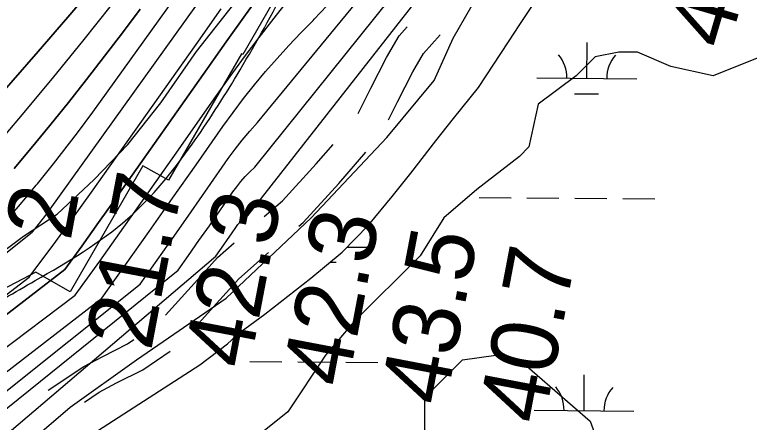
# Model space of a CAD drawing. Extents: x 3271442 to 3309282, y 752266 to 777610.
# Drawn here: x 3289402 to 3290138, y 762104 to 762512 of the extents above; entities that cross this region are included whole.
import ezdxf

# ---------------------------------------------------------------- set-up
doc = ezdxf.new("R2010")
doc.units = 0
for name, color, linetype in [('V-RIVR-EDGE', 7, 'Continuous'), ('V-RIVR-RANG', 7, 'Continuous'), ('V-ROAD-CNTR', 7, 'Continuous'), ('V-RRAP-FSHR', 7, 'Continuous'), ('V-RRAP-RVMT', 7, 'Continuous'), ('V-SITE-VEGE', 7, 'Continuous'), ('V-TOPO-DPTH', 7, 'Continuous'), ('V-TOPO-MAJR', 7, 'Continuous'), ('V-TOPO-MINR', 7, 'Continuous'), ('V-TOPO-WATR', 7, 'Continuous'), ('V-WETL-SWMP', 7, 'Continuous')]:
    doc.layers.add(name, color=color, linetype=linetype)

msp = doc.modelspace()

# ---------------------------------------------------------------- linework, layer by layer
at = {"layer": 'V-RIVR-EDGE'}
msp.add_lwpolyline([(3289379.09, 762266.5), (3289410.88, 762289.9), (3289444.84, 762311.98), (3289481.88, 762346.66), (3289515.43, 762381.79), (3289548.57, 762423.44), (3289584.34, 762475.08), (3289630.13, 762533.64), (3289660.19, 762562.26), (3289673.75, 762594.39), (3289701.73, 762662.13), (3289707, 762682.55), (3289727.55, 762729.01), (3289737.6, 762751.59), (3289752.44, 762776.33), (3289772.05, 762795.84), (3289795.16, 762824.04), (3289831.33, 762864.37), (3289858.8, 762898.21), (3289943.82, 763003.19), (3289978.7, 763046.14), (3290011.41, 763088.22), (3290036.7, 763119.89)], dxfattribs=at)
at = {"layer": 'V-ROAD-CNTR'}
for points in [[(3289745.91, 762413.02), (3289758.8, 762438.14), (3289774.28, 762468.94), (3289786.95, 762490.54), (3289795.09, 762499.69)], [(3289776.38, 762406.69), (3289785.55, 762424.56), (3289800.64, 762454.6), (3289811.33, 762472.81), (3289828.07, 762491.62)], [(3289652.03, 762309.69), (3289670.15, 762325.39), (3289704.1, 762362.56), (3289720.9, 762381.98)], [(3289686.64, 762299.98), (3289691.12, 762303.86), (3289726.53, 762342.63), (3289753.72, 762374.07)], [(3289553.18, 762210.9), (3289585.36, 762246.28), (3289605.31, 762268.74), (3289621.93, 762283.35)], [(3289586.3, 762202.72), (3289607.67, 762226.22), (3289626.51, 762247.44), (3289656.44, 762273.75)], [(3289435.69, 762135.84), (3289471.25, 762159.53), (3289490.27, 762169.68), (3289515.08, 762182.17), (3289521.63, 762186.65)], [(3289471.98, 762123.97), (3289486.66, 762133.75), (3289504.08, 762143.05), (3289530.36, 762156.27), (3289557.77, 762175)]]:
    msp.add_lwpolyline(points, dxfattribs=at)
at = {"layer": 'V-RRAP-FSHR'}
msp.add_spline([(3289175.29, 762139.24), (3289199.42, 762153.42), (3289238.78, 762167.31), (3289290.78, 762181.41), (3289361.33, 762211.47), (3289422.74, 762245.58), (3289515.55, 762307.77), (3289579.91, 762382.16), (3289624.81, 762451.54), (3289672.32, 762536.12), (3289709.18, 762613.43), (3289742.72, 762696.07), (3289778.16, 762754.9), (3289819.53, 762799.05), (3289911.37, 762921.92), (3289994.15, 763031.19), (3290081.23, 763125.2), (3290188.83, 763225.81), (3290291.39, 763333.07), (3290344.49, 763399.52), (3290388.71, 763467.2), (3290474.09, 763575.32), (3290571.03, 763693.18), (3290669.81, 763810.12), (3290775.65, 763894.02), (3290904.09, 763991.91), (3291011.39, 764077.28), (3291099.77, 764130.44), (3291153.65, 764153.45), (3291210.45, 764195.78), (3291300.74, 764249.03), (3291400.46, 764351.43), (3291483.31, 764483.33), (3291547.71, 764562.33), (3291620.77, 764622.94), (3291661.95, 764638.83), (3291706.23, 764608.33), (3291755.42, 764603.5), (3291805.88, 764628.53)], degree=3, dxfattribs=at)
at = {"layer": 'V-RRAP-RVMT'}
msp.add_lwpolyline([(3289782.89, 762774.11), (3289765.12, 762742.65), (3289769.04, 762740.59), (3289696.71, 762612.64), (3289708.05, 762606.49), (3289630.74, 762471.8), (3289629.11, 762472.45), (3289556.22, 762345.96), (3289530.62, 762360.44), (3289457.6, 762234.41), (3289423.22, 762254.14), (3289287.65, 762182.88), (3289282.8, 762191.34), (3289138.04, 762138.06), (3289132.84, 762151), (3289131.61, 762149.66), (3289126.06, 762153.92), (3289103.84, 762129.78), (3289091.6, 762108.39), (3289090.33, 762108.87), (3289016.46, 761984.19)], dxfattribs=at)
at = {"layer": 'V-SITE-VEGE'}
for points in [[(3289424.62, 762090.48), (3289457.75, 762118.91), (3289524.02, 762166.28), (3289613.95, 762227.86), (3289699.15, 762308.39), (3289774.89, 762388.92), (3289822.22, 762445.77), (3289841.15, 762488.4), (3289879.02, 762554.72), (3289888.49, 762578.41), (3289912.15, 762639.99), (3289954.75, 762696.83), (3289987.89, 762729.99), (3290011.56, 762772.63), (3290021.02, 762820), (3290039.95, 762838.95), (3290087.29, 762857.9), (3290129.89, 762867.37), (3290172.49, 762886.32), (3290191.42, 762914.74), (3290200.89, 762943.16), (3290219.82, 762976.32), (3290286.09, 762971.59)], [(3290148.82, 762469.45), (3290101.49, 762450.51), (3290058.89, 762459.98), (3290025.76, 762474.19), (3290006.82, 762474.19), (3289983.16, 762469.45), (3289964.22, 762450.51), (3289926.36, 762422.08), (3289916.89, 762379.45), (3289907.42, 762369.97), (3289864.82, 762336.81), (3289831.69, 762308.39), (3289808.02, 762270.49), (3289741.75, 762204.17), (3289713.36, 762171.01), (3289675.49, 762114.17), (3289651.82, 762095.22)], [(3289812.76, 762090.48), (3289812.76, 762128.38), (3289850.62, 762166.28), (3289883.76, 762171.01), (3289907.42, 762166.28), (3289978.42, 762104.69), (3290016.29, 762000.48)]]:
    msp.add_lwpolyline(points, dxfattribs=at)
at = {"layer": 'V-TOPO-DPTH'}
for p, q in [((3289652.3, 762538.37), (3289633.11, 762511.5)), ((3289633.11, 762511.5), (3289614, 762484.57)), ((3289614, 762484.57), (3289594.94, 762457.61)), ((3289594.94, 762457.61), (3289519.81, 762350.97)), ((3289519.81, 762350.97), (3289503.05, 762327.3)), ((3289503.05, 762327.3), (3289486.22, 762303.68)), ((3289486.22, 762303.68), (3289469.27, 762280.15)), ((3289469.27, 762280.15), (3289452.25, 762256.67)), ((3289452.25, 762256.67), (3288888.22, 761821.31))]:
    msp.add_line(p, q, dxfattribs=at)
for points in [[(3289932.87, 763104.96), (3289918.08, 763087.22), (3289911.84, 763079.77), (3289893.92, 763058.32), (3289876.06, 763036.82), (3289858.29, 763015.24), (3289840.59, 762993.61), (3289639.83, 762747.25), (3289540.75, 762615.75), (3289512.95, 762579.75), (3289484.61, 762544.19), (3289455.44, 762509.3), (3289425.73, 762474.86), (3289375.21, 762417.66)], [(3289932.87, 763104.96), (3289918.08, 763087.22), (3289911.84, 763079.77), (3289893.92, 763058.32), (3289876.06, 763036.82), (3289858.29, 763015.24), (3289840.59, 762993.61), (3289639.83, 762747.25), (3289540.75, 762615.75), (3289512.95, 762579.75), (3289484.61, 762544.19), (3289455.44, 762509.3), (3289425.73, 762474.86), (3289375.21, 762417.66)], [(3288826.37, 761820.42), (3289419.78, 762294), (3289422.33, 762297.07), (3289424.85, 762300.16), (3289427.32, 762303.29), (3289429.76, 762306.44), (3289431.34, 762308.51), (3289432.95, 762310.66), (3289434.56, 762312.81), (3289436.14, 762314.98), (3289437.72, 762317.15), (3289594.71, 762536.11)], [(3288826.37, 761820.42), (3289419.78, 762294), (3289422.33, 762297.07), (3289424.85, 762300.16), (3289427.32, 762303.29), (3289429.76, 762306.44), (3289431.34, 762308.51), (3289432.95, 762310.66), (3289434.56, 762312.81), (3289436.14, 762314.98), (3289437.72, 762317.15), (3289594.71, 762536.11)], [(3289401.78, 762357.89), (3289418.72, 762378.23), (3289437.43, 762400.98), (3289455.95, 762423.87), (3289474.19, 762447), (3289492.23, 762470.27), (3289510.02, 762493.75), (3289527.66, 762517.33)], [(3289527.66, 762517.33), (3289510.02, 762493.75), (3289492.23, 762470.27), (3289474.19, 762447), (3289455.95, 762423.87), (3289437.43, 762400.98), (3289418.72, 762378.23), (3289401.78, 762357.89)]]:
    msp.add_lwpolyline(points, dxfattribs=at)
at = {"layer": 'V-TOPO-MAJR'}
for p, q in [((3289645.29, 762403.72), (3289824.14, 762621.27)), ((3289637.52, 762395.1), (3289645.29, 762403.72)), ((3289630.01, 762386.26), (3289637.52, 762395.1)), ((3289622.89, 762377.1), (3289630.01, 762386.26)), ((3289616.04, 762367.72), (3289622.89, 762377.1)), ((3289595.62, 762338.44), (3289616.04, 762367.72)), ((3289578.74, 762314.28), (3289595.62, 762338.44)), ((3289561.83, 762290.14), (3289578.74, 762314.28)), ((3289544.88, 762266.02), (3289561.83, 762290.14)), ((3289527.91, 762241.93), (3289544.88, 762266.02)), ((3288972.93, 761798.85), (3289527.91, 762241.93))]:
    msp.add_line(p, q, dxfattribs=at)
at = {"layer": 'V-TOPO-MINR'}
for p, q in [((3289635.9, 762310.99), (3289898.78, 762646.45)), ((3289642.51, 762358.99), (3289862.76, 762633.56)), ((3289633.11, 762511.5), (3289652.3, 762538.37)), ((3289662.07, 762508.44), (3289675.27, 762525.18)), ((3289702.06, 762507.32), (3289714.63, 762520.6)), ((3289583.71, 762481.89), (3289608.75, 762517.68)), ((3289614, 762484.57), (3289633.11, 762511.5)), ((3289647.08, 762489.1), (3289662.07, 762508.44)), ((3289688.68, 762493.61), (3289700.87, 762506.13)), ((3289700.87, 762506.13), (3289702.06, 762507.32)), ((3289632.31, 762469.59), (3289647.08, 762489.1)), ((3289676.67, 762480.92), (3289688.68, 762493.61)), ((3289479.14, 762334.17), (3289583.71, 762481.89)), ((3289594.94, 762457.61), (3289614, 762484.57)), ((3289664.93, 762467.98), (3289676.67, 762480.92)), ((3289617.87, 762449.84), (3289632.31, 762469.59)), ((3289653.38, 762454.87), (3289664.93, 762467.98)), ((3289519.81, 762350.97), (3289594.94, 762457.61)), ((3289642.18, 762441.47), (3289653.38, 762454.87)), ((3289603.65, 762429.92), (3289617.87, 762449.84)), ((3289631.25, 762427.85), (3289642.18, 762441.47)), ((3289559.92, 762367.61), (3289603.65, 762429.92)), ((3289620.75, 762413.91), (3289631.25, 762427.85)), ((3289610.52, 762399.75), (3289620.75, 762413.91)), ((3289583.74, 762361.47), (3289610.52, 762399.75)), ((3289535.79, 762333.36), (3289559.92, 762367.61)), ((3289560.3, 762328.03), (3289583.74, 762361.47)), ((3289637.66, 762354.46), (3289642.51, 762358.99)), ((3289503.05, 762327.3), (3289519.81, 762350.97)), ((3289628.62, 762344.78), (3289633.05, 762349.7)), ((3289633.05, 762349.7), (3289637.66, 762354.46)), ((3289624.49, 762339.61), (3289628.62, 762344.78)), ((3289620.54, 762334.28), (3289624.49, 762339.61)), ((3289469.88, 762321.18), (3289479.14, 762334.17)), ((3289486.22, 762303.68), (3289503.05, 762327.3)), ((3289511.59, 762299.16), (3289535.79, 762333.36)), ((3289536.8, 762294.64), (3289560.3, 762328.03)), ((3289607.43, 762315.43), (3289620.54, 762334.28)), ((3289460.57, 762308.23), (3289469.88, 762321.18)), ((3289597.06, 762300.55), (3289607.43, 762315.43)), ((3289451.16, 762295.35), (3289460.57, 762308.23)), ((3289628.73, 762305.09), (3289630.41, 762306.7)), ((3289630.41, 762306.7), (3289632.18, 762308.2)), ((3289632.18, 762308.2), (3289634.01, 762309.64)), ((3289634.01, 762309.64), (3289635.9, 762310.99)), ((3289469.27, 762280.15), (3289486.22, 762303.68)), ((3289487.28, 762265.05), (3289511.59, 762299.16)), ((3289586.69, 762285.69), (3289597.06, 762300.55)), ((3289619.18, 762292.43), (3289624.27, 762299.76)), ((3289624.27, 762299.76), (3289625.66, 762301.62)), ((3289625.66, 762301.62), (3289627.13, 762303.41)), ((3289627.13, 762303.41), (3289628.73, 762305.09)), ((3289441.7, 762282.51), (3289451.16, 762295.35)), ((3289513.22, 762261.3), (3289536.8, 762294.64)), ((3289615.3, 762286.85), (3289619.18, 762292.43)), ((3289576.3, 762270.83), (3289586.69, 762285.69)), ((3289611.42, 762281.27), (3289615.3, 762286.85)), ((3289431.48, 762268.72), (3289441.7, 762282.51)), ((3289452.25, 762256.67), (3289469.27, 762280.15)), ((3289607.54, 762275.69), (3289611.42, 762281.27)), ((3289059.12, 761807.08), (3289603.65, 762270.11)), ((3289416.71, 762249.13), (3289431.48, 762268.72)), ((3289565.91, 762255.98), (3289576.3, 762270.83)), ((3289603.65, 762270.11), (3289607.54, 762275.69)), ((3289462.88, 762230.99), (3289487.28, 762265.05)), ((3289489.59, 762228), (3289513.22, 762261.3)), ((3288888.22, 761821.31), (3289452.25, 762256.67)), ((3289053.15, 761843.51), (3289565.91, 762255.98)), ((3288857.01, 761820.9), (3289416.71, 762249.13)), ((3288920.21, 761821.61), (3289462.88, 762230.99)), ((3288942.99, 761806.47), (3289489.59, 762228))]:
    msp.add_line(p, q, dxfattribs=at)
for points in [[(3289375.21, 762417.66), (3289425.73, 762474.86), (3289455.44, 762509.3), (3289484.61, 762544.19), (3289512.95, 762579.75), (3289540.75, 762615.75), (3289639.83, 762747.25), (3289840.59, 762993.61), (3289858.29, 763015.24), (3289876.06, 763036.82), (3289893.92, 763058.32), (3289911.84, 763079.77), (3289918.08, 763087.22), (3289932.87, 763104.96)], [(3289397.09, 762309.29), (3289406.1, 762319.8), (3289415, 762330.41), (3289423.82, 762341.08), (3289424.9, 762342.39), (3289433.08, 762352.49), (3289441.2, 762362.64), (3289449.22, 762372.86), (3289457.19, 762383.13), (3289465.05, 762393.48), (3289472.85, 762403.88), (3289480.55, 762414.35), (3289488.18, 762424.88), (3289605.95, 762588.98)], [(3289352.26, 762343.82), (3289411.73, 762413.98), (3289441.34, 762449.45), (3289470.57, 762485.22), (3289499.24, 762521.44)], [(3289401.78, 762357.89), (3289418.72, 762378.23), (3289437.43, 762400.98), (3289455.95, 762423.87), (3289474.19, 762447), (3289492.23, 762470.27), (3289510.02, 762493.75), (3289527.66, 762517.33)]]:
    msp.add_lwpolyline(points, dxfattribs=at)
at = {"layer": 'V-TOPO-WATR'}
msp.add_lwpolyline([(3288826.37, 761820.42), (3289419.78, 762294), (3289422.33, 762297.07), (3289424.85, 762300.16), (3289427.32, 762303.29), (3289429.76, 762306.44), (3289431.34, 762308.51), (3289432.95, 762310.66), (3289434.56, 762312.81), (3289436.14, 762314.98), (3289437.72, 762317.15), (3289594.71, 762536.11)], dxfattribs=at)
at = {"layer": 'V-WETL-SWMP'}
for p, q in [((3289907.72, 762502.1), (3289951.58, 762567.85)), ((3289896.44, 762484.73), (3289907.72, 762502.1)), ((3289866.37, 762438.82), (3289896.44, 762484.73)), ((3289974.87, 762448.04), (3289975.16, 762484.04)), ((3289924.87, 762448.46), (3290024.87, 762447.63)), ((3289841.34, 762407.83), (3289866.37, 762438.82)), ((3289962.74, 762432.71), (3289986.74, 762432.52)), ((3289823.82, 762385.51), (3289841.34, 762407.83)), ((3289798.78, 762353.27), (3289823.82, 762385.51)), ((3289780.01, 762329.71), (3289798.78, 762353.27)), ((3289756.23, 762301.2), (3289780.01, 762329.71)), ((3289867.04, 762328.86), (3289899.04, 762328.59)), ((3289915.04, 762328.46), (3289947.04, 762328.2)), ((3289963.03, 762328.07), (3289995.03, 762327.8)), ((3290011.03, 762327.67), (3290043.03, 762327.41)), ((3289729.98, 762273.94), (3289756.23, 762301.2)), ((3289735.05, 762279.2), (3289762.03, 762278.98)), ((3289698.75, 762247.95), (3289729.98, 762273.94)), ((3289717.93, 762263.91), (3289723.91, 762263.86)), ((3289652.54, 762212.07), (3289698.75, 762247.95)), ((3289627.57, 762193.52), (3289652.54, 762212.07)), ((3289615.08, 762182.38), (3289627.57, 762193.52)), ((3289587.6, 762161.35), (3289615.08, 762182.38)), ((3289480.27, 762092.15), (3289587.6, 762161.35)), ((3289637.68, 762164.57), (3289669.68, 762164.3)), ((3289685.68, 762164.17), (3289717.67, 762163.91)), ((3289733.67, 762163.78), (3289765.67, 762163.51)), ((3289972.13, 762115.38), (3289972.42, 762151.38)), ((3289922.13, 762115.79), (3290022.13, 762114.97))]:
    msp.add_line(p, q, dxfattribs=at)
for centre, start, end in [((3289919.63, 762448.97), 358.75626, 40.29992), ((3290030.11, 762448.06), 138.75625, 180.29991), ((3289916.89, 762116.31), 358.75626, 40.29992), ((3290027.37, 762115.4), 138.75625, 180.29991)]:
    msp.add_arc(centre, 35.25, start, end, dxfattribs=at)

# ---------------------------------------------------------------- texts
at = {"layer": 'V-RIVR-RANG'}
for s, rotation, p in [('41.0', 73.63833, (3290115.96, 762475.14)), ('21.7', 79.21833, (3289538.63, 762174.21)), ('2', 79.50625, (3289457.92, 762284.28)), ('42.3', 79.21833, (3289636.91, 762155.76)), ('42.3', 79.21833, (3289735.19, 762137.3)), ('43.5', 79.21833, (3289833.47, 762118.84)), ('40.7', 79.21833, (3289931.75, 762100.39))]:
    msp.add_text(s, height=67, rotation=rotation, dxfattribs=at).set_placement(p)

doc.saveas('drawing.dxf')
